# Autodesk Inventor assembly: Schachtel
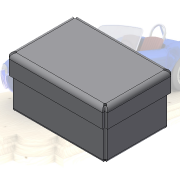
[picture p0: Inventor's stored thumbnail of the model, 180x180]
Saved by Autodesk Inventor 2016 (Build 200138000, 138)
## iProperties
Created: 2015-05
Part Number: Schachtel
Document SubType Name: Assembly
Designer: thomas
Author: thomas
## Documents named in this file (3)
- C:\Users\thomas\Documents\Inventor\Voith\2016\Schachtel.iam
- C:\Users\thomas\Documents\Inventor\Voith\2016\Schachtelboden.ipt
- C:\Users\thomas\Documents\Inventor\Voith\2016\Schachteldeckel.ipt
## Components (2 placed, 2 different names)
1. Schachtelboden:1
2. Schachteldeckel:1
